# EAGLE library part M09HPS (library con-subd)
SUB-D
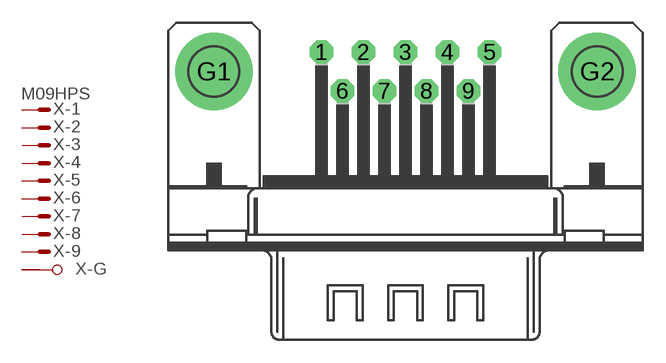
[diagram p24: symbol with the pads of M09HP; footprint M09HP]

Designator prefix X; gates -2=M -3=M -4=M -5=M -6=M -7=M -8=M -9=M -G=GND -1=MV

## M09HPS (OC_FARNELL: unknown; OC_NEWARK: unknown)  [M09HP]
1  -1:M  pas
2  -2:M  pas
3  -3:M  pas
4  -4:M  pas
5  -5:M  pas
6  -6:M  pas
7  -7:M  pas
8  -8:M  pas
9  -9:M  pas
G1  -G:G1  pas
G2  -G:G2  pas

## Footprint M09HP (pad centres in mm)
SUB-D
drill 1.016 octagon: 1 -5.486,1.27; 2 -2.743,1.27; 3 0,1.27; 4 2.743,1.27; 5 5.486,1.27; 6 -4.115,-1.27; 7 -1.372,-1.27; 8 1.372,-1.27; 9 4.115,-1.27
drill 3.302 pad 5.08 round: G1 -12.522,0; G2 12.522,0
